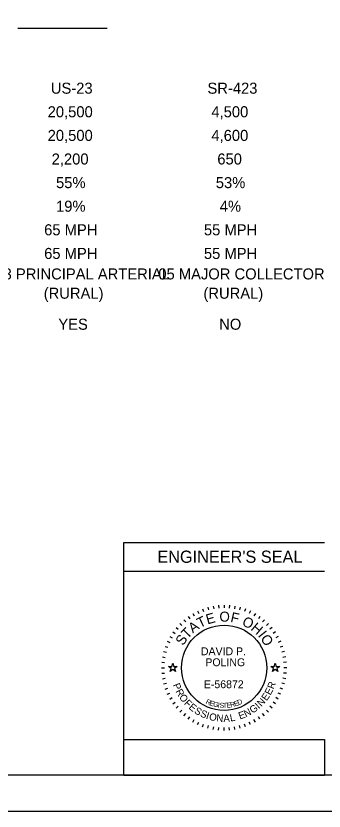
# Model space of a CAD drawing. Extents: x 0 to 34, y 0 to 22.
# Drawn here: x 7.72 to 12.03, y 0 to 11.1 of the extents above; entities that cross this region are included whole.
import ezdxf

# ---------------------------------------------------------------- set-up
doc = ezdxf.new("R2010")
doc.units = 0
for name, color, linetype in [('Default', 7, 'Continuous'), ('SH_Border', 7, 'Continuous'), ('SH_Cut_Line', 7, 'Continuous'), ('SH_Data', 7, 'Continuous'), ('SH_Text', 7, 'Continuous')]:
    doc.layers.add(name, color=color, linetype=linetype)

msp = doc.modelspace()

# ---------------------------------------------------------------- linework, layer by layer
at = {"layer": 'Default'}
for points in [[(9.857, 2.02), (9.904, 2.02), (9.919, 2.065), (9.933, 2.02), (9.98, 2.02), (9.942, 1.992), (9.956, 1.948), (9.919, 1.975), (9.881, 1.948), (9.895, 1.992)], [(11.287, 2.02), (11.334, 2.02), (11.349, 2.065), (11.363, 2.02), (11.41, 2.02), (11.372, 1.992), (11.386, 1.948), (11.349, 1.975), (11.311, 1.948), (11.325, 1.992)]]:
    msp.add_lwpolyline(points, close=True, dxfattribs=at)
at = {"layer": 'SH_Border'}
msp.add_lwpolyline([(1.5, 21.5), (33.5, 21.5), (33.5, 0.5), (1.5, 0.5)], close=True, dxfattribs=at)
at = {"layer": 'SH_Cut_Line'}
msp.add_lwpolyline([(0, 0), (34, 0), (34, 22), (0, 22)], close=True, dxfattribs=at)
at = {"layer": 'SH_Data'}
for p, q in [((9, 10.922), (7.75, 10.922)), ((9.234, 0.5), (9.234, 3.75)), ((9.234, 3.75), (12.034, 3.75)), ((9.234, 3.35), (12.034, 3.35)), ((10.264, 2.793), (10.281, 2.757)), ((10.334, 2.822), (10.348, 2.785)), ((10.407, 2.845), (10.417, 2.807)), ((10.482, 2.862), (10.489, 2.822)), ((10.557, 2.872), (10.561, 2.832)), ((10.634, 2.875), (10.634, 2.835)), ((10.71, 2.872), (10.706, 2.832)), ((10.785, 2.862), (10.779, 2.822)), ((10.86, 2.845), (10.85, 2.807)), ((10.933, 2.822), (10.919, 2.785)), ((11.003, 2.793), (10.986, 2.757)), ((10.071, 2.67), (10.097, 2.64)), ((10.132, 2.717), (10.155, 2.684)), ((10.196, 2.758), (10.216, 2.723)), ((11.071, 2.758), (11.051, 2.723)), ((11.135, 2.717), (11.112, 2.684)), ((11.196, 2.67), (11.17, 2.64)), ((9.963, 2.562), (9.994, 2.537)), ((10.015, 2.619), (10.043, 2.59)), ((11.252, 2.619), (11.224, 2.59)), ((11.304, 2.562), (11.273, 2.537)), ((9.917, 2.502), (9.95, 2.479)), ((11.35, 2.502), (11.318, 2.479)), ((9.84, 2.37), (9.877, 2.353)), ((9.876, 2.438), (9.91, 2.418)), ((11.391, 2.438), (11.357, 2.418)), ((11.427, 2.37), (11.39, 2.353)), ((9.788, 2.226), (9.827, 2.216)), ((9.811, 2.299), (9.849, 2.286)), ((11.456, 2.299), (11.418, 2.286)), ((11.479, 2.226), (11.44, 2.216)), ((9.772, 2.152), (9.811, 2.145)), ((11.495, 2.152), (11.456, 2.145)), ((9.759, 2), (9.799, 2)), ((9.762, 2.076), (9.802, 2.073)), ((11.505, 2.076), (11.465, 2.073)), ((11.509, 2), (11.469, 2)), ((9.762, 1.924), (9.802, 1.927)), ((11.505, 1.924), (11.465, 1.927)), ((9.772, 1.848), (9.811, 1.855)), ((9.788, 1.774), (9.827, 1.784)), ((11.479, 1.774), (11.44, 1.784)), ((11.495, 1.848), (11.456, 1.855)), ((9.811, 1.701), (9.849, 1.714)), ((11.456, 1.701), (11.418, 1.714)), ((9.84, 1.63), (9.877, 1.647)), ((9.876, 1.563), (9.91, 1.583)), ((11.391, 1.563), (11.357, 1.583)), ((11.427, 1.63), (11.39, 1.647)), ((9.917, 1.498), (9.95, 1.521)), ((9.963, 1.438), (9.994, 1.463)), ((11.304, 1.438), (11.273, 1.463)), ((11.35, 1.498), (11.318, 1.521)), ((10.015, 1.381), (10.043, 1.41)), ((10.071, 1.33), (10.097, 1.36)), ((11.196, 1.33), (11.17, 1.36)), ((11.252, 1.381), (11.224, 1.41)), ((10.132, 1.283), (10.155, 1.316)), ((10.196, 1.242), (10.216, 1.277)), ((10.264, 1.207), (10.281, 1.243)), ((11.003, 1.207), (10.986, 1.243)), ((11.071, 1.242), (11.051, 1.277)), ((11.135, 1.283), (11.112, 1.316)), ((10.334, 1.178), (10.348, 1.215)), ((10.407, 1.155), (10.417, 1.193)), ((10.482, 1.138), (10.489, 1.178)), ((10.557, 1.128), (10.561, 1.168)), ((10.634, 1.125), (10.634, 1.165)), ((10.71, 1.128), (10.706, 1.168)), ((10.785, 1.138), (10.779, 1.178)), ((10.86, 1.155), (10.85, 1.193)), ((10.933, 1.178), (10.919, 1.215)), ((9.234, 0.5), (12.034, 0.5))]:
    msp.add_line(p, q, dxfattribs=at)
msp.add_lwpolyline([(9.234, 0.5), (9.234, 1), (12.034, 1), (12.034, 0.5)], close=True, dxfattribs=at)
msp.add_circle((10.634, 2), 0.595, dxfattribs=at)

# ---------------------------------------------------------------- texts
for s, height, p in [("ENGINEER'S SEAL", 0.17, (9.701, 3.465)), ('DAVID P. ', 0.11, (10.31, 2.175)), ('POLING', 0.11, (10.372, 2.022)), ('E-56872', 0.11, (10.351, 1.715))]:
    msp.add_text(s, height=height, dxfattribs=at).set_placement(p)
for s, height, rotation, p in [('O', 0.14, 359.7812, (10.568, 2.644)), ('F', 0.14, 347.4362, (10.715, 2.642)), ('T', 0.14, 25.7167, (10.295, 2.552)), ('E', 0.14, 15.7571, (10.402, 2.604)), ('O', 0.14, 332.2586, (10.873, 2.602)), ('T', 0.14, 46.4344, (10.122, 2.396)), ('A', 0.14, 36.4747, (10.197, 2.478)), ('H', 0.14, 319.9136, (10.997, 2.536)), ('S', 0.14, 57.1924, (10.062, 2.301)), ('I', 0.14, 308.367, (11.1, 2.448)), ('O', 0.14, 303.1491, (11.136, 2.409)), ('P', 0.1, 291.494, (9.916, 1.762)), ('R', 0.1, 69.2322, (11.325, 1.695)), ('R', 0.1, 298.7311, (9.952, 1.672)), ('E', 0.1, 61.9951, (11.281, 1.61)), ('O', 0.1, 306.4666, (9.999, 1.588)), ('F', 0.1, 314.7068, (10.068, 1.498)), ('R', 0.07, 334.487, (10.371, 1.505)), ('D', 0.07, 23.3052, (10.835, 1.477)), ('N', 0.1, 47.0224, (11.154, 1.451)), ('E', 0.1, 54.758, (11.227, 1.531)), ('E', 0.1, 321.4393, (10.131, 1.435)), ('S', 0.1, 328.6764, (10.208, 1.375)), ('E', 0.07, 341.04, (10.424, 1.48)), ('G', 0.07, 347.4752, (10.475, 1.462)), ('I', 0.07, 353.7858, (10.543, 1.447)), ('S', 0.07, 356.8926, (10.569, 1.443)), ('T', 0.07, 3.0061, (10.619, 1.439)), ('E', 0.07, 6.0117, (10.672, 1.441)), ('R', 0.07, 11.9184, (10.726, 1.447)), ('E', 0.07, 17.6836, (10.783, 1.46)), ('G', 0.1, 35.0469, (11.032, 1.357)), ('I', 0.1, 43.287, (11.12, 1.421)), ('S', 0.1, 335.9134, (10.29, 1.327)), ('I', 0.1, 343.1505, (10.374, 1.29)), ('O', 0.1, 346.8859, (10.417, 1.275)), ('N', 0.1, 355.1261, (10.522, 1.252)), ('A', 0.1, 2.8617, (10.626, 1.244)), ('L', 0.1, 10.0987, (10.723, 1.249)), ('E', 0.1, 20.0742, (10.855, 1.277)), ('N', 0.1, 27.3113, (10.938, 1.308))]:
    msp.add_text(s, height=height, rotation=rotation, dxfattribs=at).set_placement(p)
at = {"layer": 'SH_Text'}
for s, p in [('US-23', (8.213, 10.011)), ('SR-423', (10.401, 10.011)), ('20,500', (8.169, 9.682)), ('4,500', (10.456, 9.682)), ('20,500', (8.169, 9.352)), ('4,600', (10.456, 9.352)), ('2,200', (8.225, 9.023)), ('650', (10.539, 9.023)), ('55%', (8.286, 8.693)), ('53%', (10.518, 8.693)), ('19%', (8.286, 8.364)), ('4%', (10.573, 8.364)), ('65 MPH', (8.12, 8.035)), ('55 MPH', (10.352, 8.035)), ('65 MPH', (8.12, 7.705)), ('55 MPH', (10.352, 7.705)), ('03 PRINCIPAL ARTERIAL ', (7.439, 7.419)), ('05 MAJOR COLLECTOR ', (9.715, 7.419)), ('(RURAL)', (8.114, 7.15)), ('(RURAL)', (10.345, 7.15)), ('YES', (8.318, 6.717)), ('NO', (10.565, 6.717))]:
    msp.add_text(s, height=0.154, dxfattribs=at).set_placement(p)

doc.saveas('drawing.dxf')
